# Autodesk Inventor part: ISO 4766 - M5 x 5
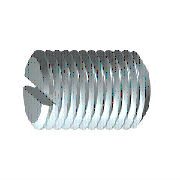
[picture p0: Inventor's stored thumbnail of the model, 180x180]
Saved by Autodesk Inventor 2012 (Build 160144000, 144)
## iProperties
IsCustomPart: 0
Created: 2008-01
Part Number: ISO 4766 - M5 x 5
Material: Stainless Steel, 440C
Description: Slotted Headless Set Screw - Flat Point
Document SubType Name: Modeling
Standard: ISO 4766
Designer: latalom
Standard Revision: First edition 1983-09-01
Standards Organization: ISO
Language: en-US
Size Designation: M5 x 5
Categories: <MemberInstance><Categories><Category DisplayName="Fasteners" InternalName="e4da775c-781d-43d5-af7c-5136215cf5a6" Mnemonic="FSTN"><Category DisplayName="Bolts"
Density: 7.75 g/cm^3
Mass: 0.682426 g
Surface Area: 1.16465 cm^2
Volume: 0.088055 cm^3
Author: latalom
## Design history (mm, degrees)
revolve "Body" stored, may be unused: angle "d6" = 90 deg
sketch "Sketch2"
  geometry: L1 (5, 2.009)-(5, -2.009) reference; L2 (3.464, 0)-(5.256, 0) reference; L3 (5, 0.4)-(3.72, 0.4); L4 (3.72, 0.4)-(3.72, 0); L5 (3.72, -0.4)-(3.72, 0); L6 (3.72, -0.4)-(5, -0.4)
  constraints: 8 end point, 3 point on line, 2 perpendicular, 1 parallel, 1 symmetric about line, 1 other
  dimensions: "d8" = 0.4 distance between parallel lines of L2 L3 (= 0.5 x SBR); "d9" = 1.28 distance between parallel lines of L1 L4 (= STI)
extrude "Slot1" cut sketch "Sketch2" stored distance "d10" = 5 (= NND); taper "d11" = 0 deg
workaxis "Work Axis1"
workplane "Work Plane1"
body "Solid1"
chamfer "Chamfer1" distance "d3" = 0.49076 (= -0.5 x GD1 + 0.5 x NND); stored, may be unused: angle "d4" = 60 deg (= FAWI), second distance "d34" = 0.49076 (= -0.5 x GD1 + 0.5 x NND)
feature "Thread" dims "d5" = 5 (= NLG), "d7" = 0
chamfer "Chamfer2" distance "d13" = 0.43301 (computed from NND, SPD, FAWI); stored, may be unused: angle "d14" = 60 deg (= FAWI), second distance "d35" = 0.43301 (computed from NND, SPD, FAWI)
sketch "Sketch1"
  geometry: L1 (0, 0)-(5, 0); L2 (5, 0)-(5, 2.5); L3 (5, 2.5)-(0, 2.5); L4 (0, -0.5)-(0, 3) reference; L5 (0, 2.5)-(0, 0)
  constraints: 9 end point, 2 parallel, 2 perpendicular, 1 collinear, 1 point on line
  dimensions: "d0" = 5 diameter of L3 L1 (= NND); "d2" = 5 distance from line of L2 L3.end (= NLG)
other parameters: "NND" = 5 [user parameter; used in 6 equation terms], "NLG" = 5 [user parameter; used in 2 equation terms], "FAWI" = 60 deg [user parameter; used in 4 equation terms], "GD1" = 4.01848 (= THREADDIA - 1.2269 x PTC) [user parameter; used in 2 equation terms], "d1" = 0, "FAWI1" = 45 deg [user parameter], "SPD" = 3.5 [user parameter; used in 2 equation terms], "SBR" = 0.8 [user parameter; used in 1 equation term], "STI" = 1.28 [user parameter; used in 1 equation term], "d15" = 0, "d36" = 90 deg, "d37" = 0, "GUL" = 0.49076 (= 0.61345 x PTC) [user parameter], "TPU" = 12.5 (computed from PTC) [user parameter], "THREADDIA" = 5 [user parameter; used in 1 equation term], "TOA" = 30 deg [user parameter], "PTC" = 0.8 [user parameter; used in 4 equation terms], "GAL" = 0.49076 (= 0.61345 x PTC) [user parameter]
